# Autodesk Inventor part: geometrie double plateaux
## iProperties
Created: 2011-12
Part Number: geometrie double plateaux
Document SubType Name: Modeling
Designer: Laur
Density: 1 g/cm^3
Author: Laur
